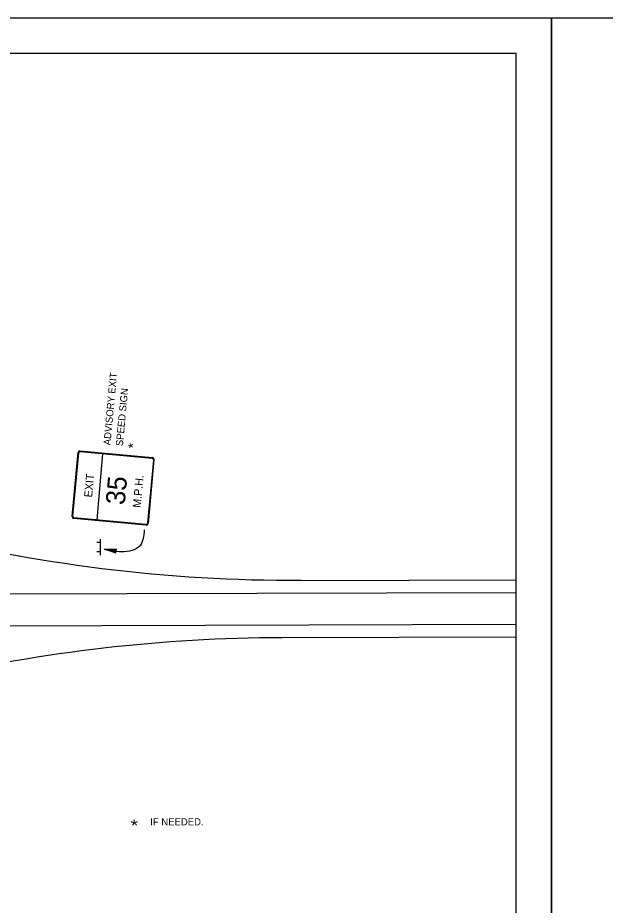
# Model space of a CAD drawing. Extents: x 640994 to 644422, y 298458 to 299646.
# Drawn here: x 643292.3 to 643539.9, y 299271.4 to 299645.6 of the extents above; entities that cross this region are included whole.
import ezdxf

# ---------------------------------------------------------------- set-up
doc = ezdxf.new("R2010")
doc.units = 0
for name, color, linetype in [('1', 7, 'Continuous'), ('2', 7, 'Continuous'), ('XCS-GRID-MIN', 7, 'Continuous')]:
    doc.layers.add(name, color=color, linetype=linetype)

msp = doc.modelspace()

# ---------------------------------------------------------------- linework, layer by layer
at = {"layer": '1'}
for p in [(642716.31, 299630.63), (643502.31, 299066.63)]:
    msp.add_line(p, (643502.31, 299630.63), dxfattribs=at)
at = {"layer": '2'}
for p, q in [((643315.19, 299435.25), (643317.69, 299462.38)), ((643315.44, 299435.5), (643317.94, 299462.13)), ((643318.44, 299463), (643349.06, 299460.13)), ((643318.56, 299462.75), (643348.94, 299459.88)), ((643325.69, 299433.88), (643328.19, 299461.75)), ((643349.44, 299459.13), (643346.94, 299432.63)), ((643349.69, 299459.38), (643347.19, 299432.38)), ((643346.44, 299431.63), (643315.81, 299434.5)), ((643346.31, 299432), (643315.94, 299434.75)), ((643326.94, 299424.38), (643325.56, 299424.38)), ((643326.94, 299425.75), (643326.94, 299419)), ((643326.94, 299420.38), (643325.56, 299420.38)), ((643326.94, 299418.63), (643326.94, 299418.63)), ((643326.94, 299418.63), (643326.94, 299418.63)), ((643411.94, 299408.38), (643502.31, 299408.64)), ((643497.06, 299408.63), (643497.06, 299408.63)), ((643099.31, 299402.13), (643502.31, 299403.27)), ((643101.31, 299388.63), (643502.31, 299389.89)), ((643403.56, 299384.25), (643502.31, 299384.52))]:
    msp.add_line(p, q, dxfattribs=at)
msp.add_lwpolyline([(643333.44, 299420.13), (643333.31, 299420.5), (643328.81, 299421.5), (643333.44, 299420.13), (643333.69, 299419.88), (643328.81, 299421.5), (643333.44, 299421), (643333.69, 299421.25), (643328.81, 299421.5), (643333.94, 299421.5), (643333.69, 299421.25)], dxfattribs=at)
for centre, start, end in [((643409.91, 300080.28), 255.77937, 270.1682), ((643405.54, 298712.33), 90.1683, 103.0152)]:
    msp.add_arc(centre, 671.88, start, end, dxfattribs=at)
for centre, major_axis, start_param, end_param in [((643318.34, 299462.27), (-0.066, -0.711), 3.141593, 4.712389), ((643318.5, 299462.04), (-0.06, -0.652), 3.141593, 4.712389), ((643348.85, 299459.23), (0.06, 0.652), 4.712389, 6.283185), ((643349.06, 299459.42), (0.066, 0.711), 4.712389, 6.283185), ((643316.04, 299435.44), (-0.06, -0.652), 4.712389, 6.283185), ((643315.83, 299435.24), (-0.066, -0.711), 4.712389, 6.283185), ((643346.38, 299432.62), (0.06, 0.652), 3.141593, 4.712389), ((643346.55, 299432.4), (-0.066, -0.711), 0, 1.570796)]:
    msp.add_ellipse(centre, major_axis=major_axis, ratio=0.9, start_param=start_param, end_param=end_param, dxfattribs=at)
msp.add_spline([(643345.56, 299429.63), (643343.81, 299423), (643335.94, 299420.38), (643328.81, 299421.5)], degree=3, dxfattribs=at)
at = {"layer": 'XCS-GRID-MIN'}
for points in [[(642676.31, 299645.63), (643517.31, 299645.63), (643517.31, 299051.63), (642676.31, 299051.63)], [(643517.31, 299645.63), (644358.31, 299645.63), (644358.31, 299051.63), (643517.31, 299051.63)]]:
    msp.add_lwpolyline(points, close=True, dxfattribs=at)

# ---------------------------------------------------------------- texts
at = {"layer": '2'}
for s, height, rotation, p in [('ADVISORY EXIT', 3, 84.7025, (643331.31, 299465.25)), ('SPEED SIGN', 3, 84.7025, (643336.56, 299464.88)), ('*', 4.32, 84.7025, (643342.88, 299463.82)), ('EXIT', 3.373, 84.7024, (643323.56, 299443.25)), ('35', 8.062, 84.7025, (643337.31, 299440)), ('M.P.H.', 3.373, 84.7031, (643344.06, 299438.88)), ('*', 5.42, 75.7789, (643344.91, 299303.85))]:
    msp.add_text(s, height=height, rotation=rotation, dxfattribs=at).set_placement(p)
msp.add_text('IF NEEDED.', height=3, dxfattribs=at).set_placement((643348.09, 299305.06))

doc.saveas('drawing.dxf')
